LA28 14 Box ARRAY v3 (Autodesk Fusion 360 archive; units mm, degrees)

design "LA28 14 Box ARRAY" references "LA28 TOUR BLOCK", "LA28 RF1 Sheet Metal Assembly"
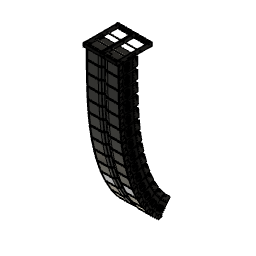
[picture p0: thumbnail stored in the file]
component_insert "Component Insert1"
as_built_joint "As-built1"
component_insert "Component Insert2"
joint "Assemble1" alignAngle 0 alignOffsetX 0 alignOffsetY 0 alignOffsetZ 5.08
component_insert "Component Insert3"
joint "Assemble2" alignAngle -0.5 alignOffsetX 0 alignOffsetY 0 alignOffsetZ 5.08
component_insert "Component Insert4"
component_insert "Component Insert5"
joint "Assemble3" alignAngle -1 alignOffsetX 0 alignOffsetY 0 alignOffsetZ 5.08
joint "Assemble4" alignAngle -1 alignOffsetX 0 alignOffsetY 0 alignOffsetZ 5.08
component_insert "Component Insert6"
component_insert "Component Insert7"
component_insert "Component Insert8"
joint "Assemble5" alignAngle -1.5 alignOffsetX 0 alignOffsetY 0 alignOffsetZ 5.08
joint "Assemble6" alignAngle -2 alignOffsetX 0 alignOffsetY 0 alignOffsetZ 5.08
joint "Assemble7" alignAngle -3 alignOffsetX 0 alignOffsetY 0 alignOffsetZ 5.08
component_insert "Component Insert9"
joint "Assemble8" alignAngle -3 alignOffsetX 0 alignOffsetY 0 alignOffsetZ 5.08
component_insert "Component Insert10"
joint "Assemble9" alignAngle -3 alignOffsetX 0 alignOffsetY 0 alignOffsetZ 5.08
component_insert "Component Insert11"
component_insert "Component Insert12"
joint "Assemble10" alignAngle -4 alignOffsetX 0 alignOffsetY 0 alignOffsetZ 5.08
joint "Assemble11" alignAngle -5 alignOffsetX 0 alignOffsetY 0 alignOffsetZ 5.08
component_insert "Component Insert13"
joint "Assemble12" alignAngle -5 alignOffsetX 0 alignOffsetY 0 alignOffsetZ 5.08
component_insert "Component Insert14"
component_insert "Component Insert15"
joint "Assemble13" alignAngle -7 alignOffsetX 0 alignOffsetY 0 alignOffsetZ 5.08
joint "Assemble14" alignAngle -11 alignOffsetX 0 alignOffsetY 0 alignOffsetZ 5.08

design "LA28 TOUR BLOCK" references "LA28 TOUR BLOCK.sldprt"
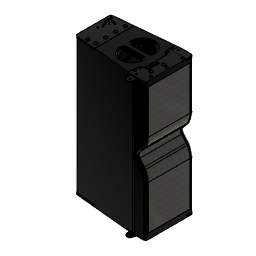
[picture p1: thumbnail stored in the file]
step "WorkingModel"
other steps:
derived_base_feature "Derived Base Feature" bodies "Fillet3"
named bodies: "Fillet3"

design "LA28 RF1 Sheet Metal Assembly" references "la28RF1 SHEET METAL ASSEMBLY.SLDASM"
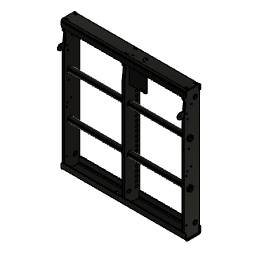
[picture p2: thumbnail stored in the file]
step "WorkingModel"
derived_instance "DerivedInstance1"
derived_instance "DerivedInstance2"
derived_instance "DerivedInstance3"
derived_instance "DerivedInstance4"
derived_instance "DerivedInstance5"
derived_instance "DerivedInstance6"
derived_instance "DerivedInstance7"
as_built_joint "As-built1"
offset_faces "OffsetFaces1" distance 0.7595 (= "0.1644 in - 0.1345 in")
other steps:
derived_base_feature "Derived Base Feature1"
derived_base_feature "Derived Base Feature1" bodies "Cut-Extrude3"
derived_base_feature "Derived Base Feature1" bodies "Cut-Extrude3"
derived_base_feature "Derived Base Feature1" bodies "Boss-Extrude1"
derived_base_feature "Derived Base Feature1" bodies "Cut-Extrude2"
derived_base_feature "Derived Base Feature1" bodies "Boss-Extrude1"
derived_base_feature "Derived Base Feature1" bodies "Cut-Extrude2"
derived_base_feature "Derived Base Feature1" bodies "Mirror2"
create_component "CreateComponent1"
create_component "CreateComponent2"
create_component "CreateComponent3"
create_component "CreateComponent4"
create_component "CreateComponent5"
create_component "CreateComponent6"
create_component "CreateComponent7"
named bodies: "Cut-Extrude3", "Cut-Extrude2", "Mirror2", "Boss-Extrude1"

design "la28RF1 SHEET METAL ASSEMBLY.SLDASM"
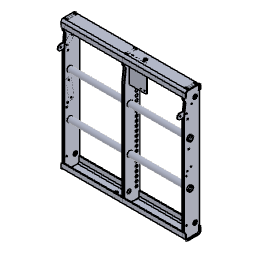
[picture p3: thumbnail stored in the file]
named bodies: "Cut-Extrude3", "Cut-Extrude2", "Mirror2", "Boss-Extrude1"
